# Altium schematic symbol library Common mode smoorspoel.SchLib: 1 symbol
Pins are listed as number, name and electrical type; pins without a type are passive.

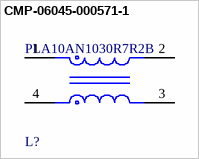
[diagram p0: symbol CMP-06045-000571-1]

## CMP-06045-000571-1
designator L?, comment PLA10AN1030R7R2B
Common Mode Choke Dual 10mH 0.7A 0.86Ω DCR Thru-Hole Bulk; Lead Diameter: 0.9mm; Voltage Rating (DC): 300V; Current: 700mA; Lead/Base Style: Pin; DC Resistance (DCR): 100mR; Shielding: Unshielded; Number of Lines: 2
footprint FP-PLA10A-PLH10A-MFG
pins: 1, 2, 3, 4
